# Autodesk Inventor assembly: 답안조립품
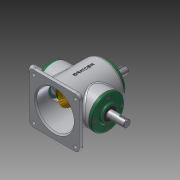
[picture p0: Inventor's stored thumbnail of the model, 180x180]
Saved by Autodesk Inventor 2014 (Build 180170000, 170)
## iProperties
Created: 2015-10
Part Number: 답안조립품
Document SubType Name: Assembly
Designer: Owner
Author: Owner
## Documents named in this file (14)
- C:\Documents and Settings\Owner\바탕 화면\451007V1011\답안조립품.iam
- C:\Documents and Settings\Owner\바탕 화면\451007V1011\본체.ipt
- C:\Documents and Settings\Owner\바탕 화면\451007V1011\오일실.ipt
- C:\Documents and Settings\Owner\바탕 화면\451007V1011\베어링 6203.ipt
- C:\Documents and Settings\Owner\바탕 화면\451007V1011\메인 축.ipt
- 메인 축.ipt
- C:\Documents and Settings\Owner\바탕 화면\451007V1011\메인 베벨기어.ipt
- C:\Documents and Settings\Owner\바탕 화면\451007V1011\커버.ipt
- C:\Documents and Settings\Owner\바탕 화면\451007V1011\키 5x5.ipt
- C:\Documents and Settings\Owner\바탕 화면\451007V1011\서브 베벨기어.ipt
- C:\Documents and Settings\Owner\바탕 화면\451007V1011\키 4x4.ipt
- C:\Documents and Settings\Owner\바탕 화면\451007V1011\서브 축.ipt
- 서브 축.ipt
- C:\Documents and Settings\Owner\바탕 화면\451007V1011\M4.ipt
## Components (12 placed, 1 different names)
1. M4:1 — 각도:6
2. M4:3 — 각도:4
3. M4:4
4. M4:5
5. M4:6
6. M4:7
7. M4:8
8. M4:9
9. M4:2 — 각도:5
10. M4:10
11. M4:11
12. M4:12
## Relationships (3: Angle 3)
- 각도:4 [Angle]: M4:3
- 각도:5 [Angle]: M4:2
- 각도:6 [Angle]: M4:1
